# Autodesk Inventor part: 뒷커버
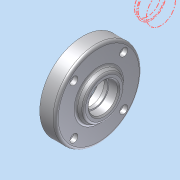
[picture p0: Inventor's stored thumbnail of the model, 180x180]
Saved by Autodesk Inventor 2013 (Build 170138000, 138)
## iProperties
Company: 한국ATC센터
Created: 2009-02
Part Number: 뒷커버
Document SubType Name: Modeling
Designer: KYOUNG IL JANG
Density: 2.71 g/cm^3
Mass: 97.9591 g
Surface Area: 115.525 cm^2
Volume: 36.1473 cm^3
Material: 알루미늄-6061
Vendor: CBT Solutions
Author: KYOUNG IL JANG
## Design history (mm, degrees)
sketch "스케치1"
  geometry: L1 (-10.5, 0)-(10.5, 0); L2 (10.5, 0)-(10.5, 22.5); L3 (10.5, 22.5)-(5.5, 22.5); L4 (5.5, 22.5)-(5.5, 32.5); L5 (5.5, 32.5)-(-6.5, 32.5); L6 (-6.5, 32.5)-(-6.5, 17.5); L7 (-6.5, 17.5)-(-10.5, 15.191); L8 (-10.5, 15.191)-(-10.5, 0); 2 further points
  constraints: 16 end point, 3 parallel, 3 perpendicular, 1 coincident, 1 horizontal, 1 midpoint
  dimensions: "d0" = 21 distance of L1.start L1.end; "d1" = 65 diameter of L5 L1; "d2" = 45 diameter of L3 L1; "d3" = 35 diameter of L6.end L1; "d4" = 120 deg angle of L7 L6; "d5" = 12 distance of L4.end L5.end; "d6" = 5 distance of L2.end L3.end
revolve "회전1" sketch "스케치1" stored, may be unused: angle "d7" = 90 deg
sketch "스케치2"
  geometry: L1 (0, 0)-(32.5, 0); L2 (0, 0)-(18.738, 18.738); 1 further point
  constraints: 4 end point, 1 horizontal, 1 horizontal alignment, 1 other
  dimensions: "d8" = 45 deg angle of L1 L2; "d9" = 26.5 distance of L1.start L2.end
hole "구멍1" sketch "스케치2" at (18.738, 18.738) diameter "d10" = 3.4; stored, may be unused: countersink angle "d14" = 90 deg, drill point angle "d16" = 118 deg; dims "d11" = 6, "d12" = 6, "d13" = 3.3, "d15" = 8
fillet "모깎기1" dims "d20" = 2
hole "구멍2" diameter "d23" = 15; stored, may be unused: countersink angle "d27" = 90 deg, drill point angle "d29" = 0 deg; dims "d21" = 10, "d22" = 10, "d24" = 6, "d25" = 35, "d26" = 11, "d28" = 14
chamfer "모따기1" distance "d39" = 1; stored, may be unused: second distance "d40" = 2, angle "d41" = 45 deg
fillet "모깎기2" dims "d42" = 0.3
hole "구멍4" diameter "d46" = 17; stored, may be unused: countersink angle "d50" = 90 deg, drill point angle "d52" = 118 deg; dims "d44" = 10, "d45" = 10, "d47" = 6, "d48" = 22, "d49" = 7.3, "d51" = 8
chamfer "모따기2" distance "d53" = 1; stored, may be unused: second distance "d54" = 2, angle "d55" = 45 deg
fillet "모깎기3" dims "d56" = 0.3
node "솔리드1"
pattern_circular "원형 패턴1" dims angle "d18" = 360 deg
